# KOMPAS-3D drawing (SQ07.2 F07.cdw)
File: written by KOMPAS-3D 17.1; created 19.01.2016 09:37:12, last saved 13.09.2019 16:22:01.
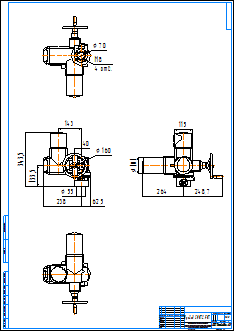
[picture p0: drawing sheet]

Sheet 1: A1, portrait

Title block, sheet 1: name: Привод SQ07.2 F07; material: Внимание! Данный продукт является объектом авторского права ООО «Торговый Дом АДЛ». / Запрещается изменение, копирование, распространение / (в том числе путем копирования на другие сайты и ресурсы в Интернете) / или любое иное использование информации и объектов без предварительного / согласия правообладателя (ООО «Торговый Дом АДЛ»).; sheets: 1; organisation: ООО "Торговый дом АДЛ"; sheet format: A1; stored path: \\adlc.lan\data\АДЛ_ПКД\3D-модели\Поставщики\Сервоприводы AUMA\Электроприводы серии SQ\KOMPAS 2D\Привод SQ07.2 F07.cdw

Views: Вид 1, Проекционный вид 2, Проекционный вид 3, Проекционный вид 4
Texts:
  Klimkovich
  ADL
Dimensions and other numbers on the sheet: 343,5; 160; 133,5; 62,5; 238; 40; 143; 55; 248,7; 264; 115; 101; 70; 8; 4 отв.; 1:2,5; 1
